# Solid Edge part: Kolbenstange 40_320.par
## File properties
Username: ahadarics
Dokumentum tartalom típus: 0
Author: ahadarics
Last saved by: ahadarics
Revision: 88
Sűrűség: 0,000 kg/m^3
Pontosság: 0,990
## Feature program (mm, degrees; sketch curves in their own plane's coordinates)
base feature "unnamed BaseFeature 1"
thread "unnamed Thread 1"
chamfer "Letörés_1"  SetBackValue2 = 20 deg
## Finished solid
Body 1: solid body, 21 faces, 32 edges, 14 vertices.
  Faces by surface: plane 8, cylinder 5, cone 4, torus 4
  Edges by curve: circle 17, line 9, curve on surface 4, ellipse 2
Bounding box of the edges (mm; curved faces can reach further): 40.000 x 40.000 x 448.000, from (-20, -20, -78) to (20, 20, 370).
Cylindrical faces by radius (mm): R5 x1, R6 x1, R7.75 x1, R8 x1, R20 x1
Conical faces (half-angle, radius in mm at the cone's reference point): 20 deg R6 x1, 30 deg R7.875 x1, 45 deg R19.6 x1, 60 deg R5.5 x1
Toroidal faces (ring radius, tube radius in mm): R5.4 r0.4 x2, R6.55 r1.2 x2
Planar faces by outward normal: +x 1, +z 3, -x 1, -z 1, oblique 2
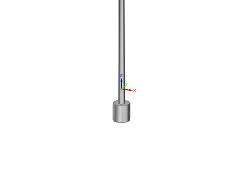
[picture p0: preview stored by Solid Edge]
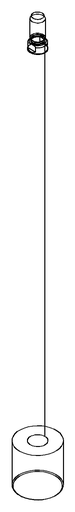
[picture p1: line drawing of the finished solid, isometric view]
